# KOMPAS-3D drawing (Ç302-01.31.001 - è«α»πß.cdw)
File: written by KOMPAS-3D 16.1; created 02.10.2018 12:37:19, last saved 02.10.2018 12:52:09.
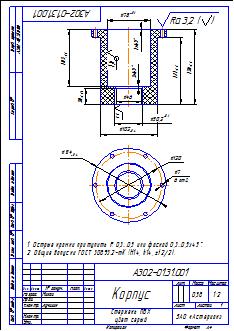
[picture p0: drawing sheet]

Sheet 1: A4, portrait

Title block, sheet 1: name: Корпус; designation: А302-01.31.001; mass: 0,58; scale: 1:2; sheets: 1; organisation: ЗАО «Астерион»; sheet format: A4; stored path: \\192.168.87.28\Konstructor_doc\Мембранные насосы\Мембранный электропривод\А302-00.00.000 - ASTRA-302 (МЭ200)\3Д ПВХ\А302-01.31.001 - Корпус.cdw; drawn by: Милов; technical control: Лучихин

Views: Вид 1, Местный разрез 1, Вид:1, Проекционный вид 2
Referenced files in \\192.168.87.28\Konstructor_doc\Мембранные насосы\Мембранный электропривод\А302-00.00.000 - ASTRA-302 (МЭ200)\3Д ПВХ\: А302-01.31.001 - Корпус.m3d
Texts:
  Стержень ПВХ
  цвет серый
  Острые кромки притупить R 0,3...0,5 или фаской 0,3...0,5х45 .
  Общие допуски ГОСТ 30893.2-mK (H14, h14,  t2/2).
  Ra 3,2
  Ra 3,2 ( )
Dimensions and other numbers on the sheet: 1; 3; 50,2; 102; 121; 136; 103; 46; 78; 30; 1,6; 0,8; 120; 7; 6 отв.; 134; 1:2; 0,58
